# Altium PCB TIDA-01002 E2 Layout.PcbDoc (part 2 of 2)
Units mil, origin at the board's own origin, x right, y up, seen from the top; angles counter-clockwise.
Board outline 1055.12 x 1877.5 mil, 6 copper layers (Layer 1 - Top Layer, Layer 2 - GND, Layer 3 - Signal, Layer 4 - Signal 2, Layer 5 - GND, Layer 6 - Bottom Layer), stack 61.268 mil thick; 83 components, 52 nets, 333 pads, 146 vias.
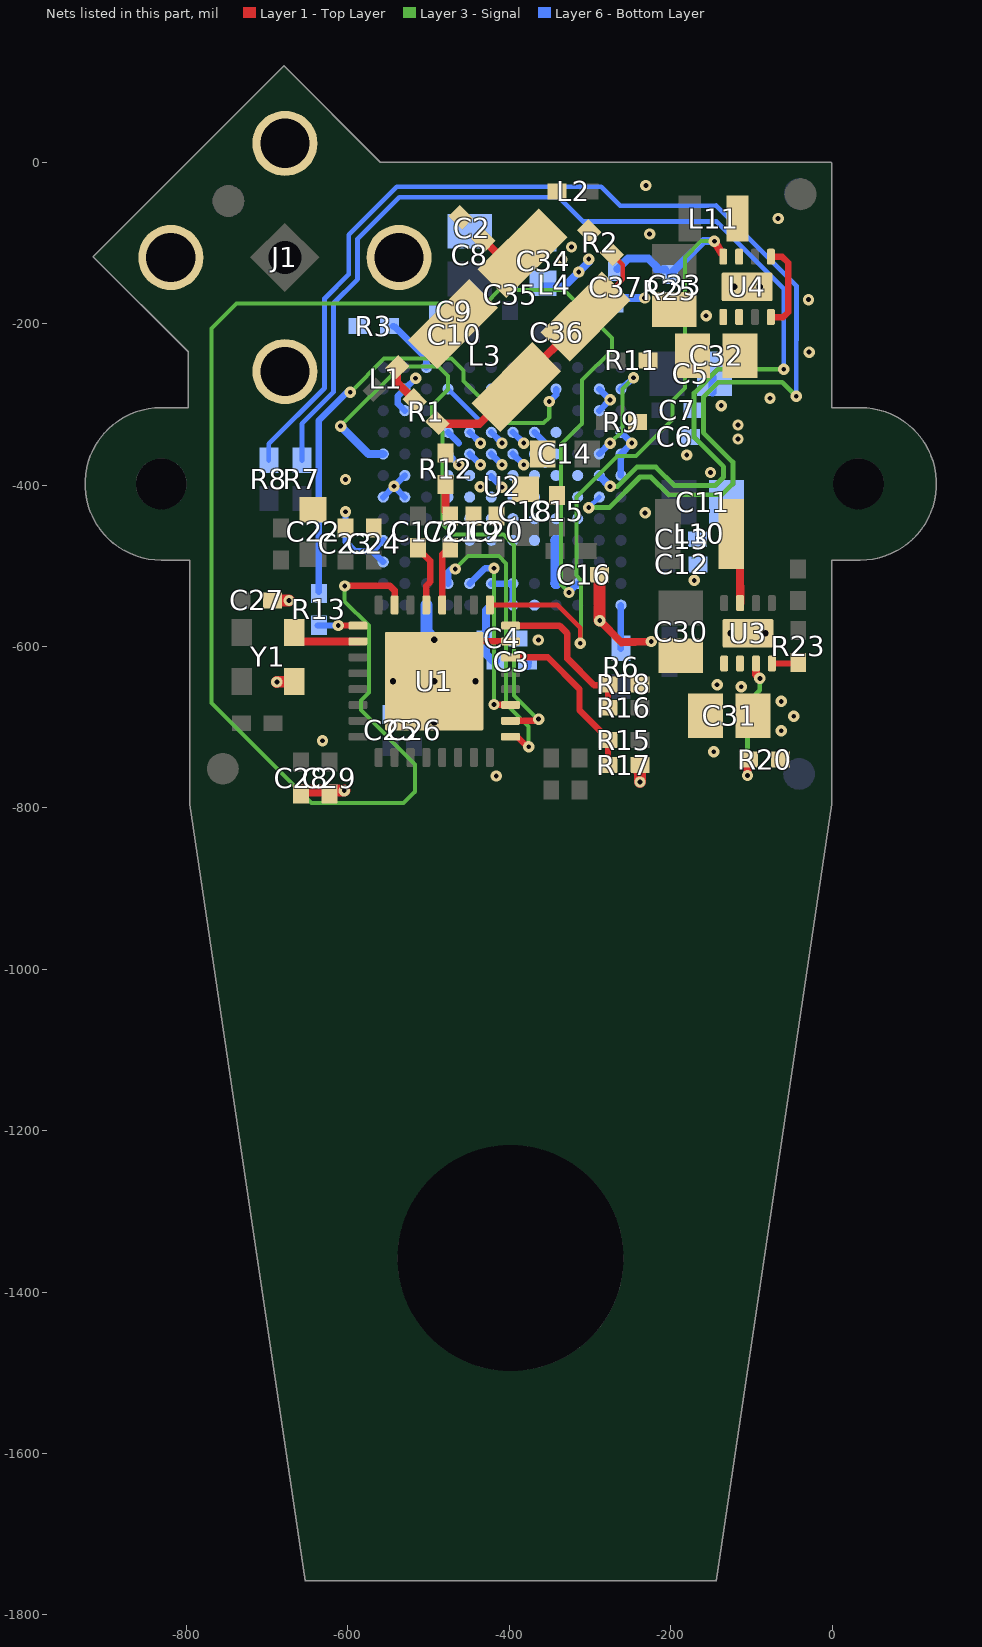
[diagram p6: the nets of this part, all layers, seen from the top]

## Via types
v1: diameter 14, hole 6, Layer 1 - Top Layer to Layer 6 - Bottom Layer, tented both sides, 137 vias
v2: diameter 19.68, hole 7.87, Layer 1 - Top Layer to Layer 6 - Bottom Layer, tented both sides, 5 vias
v3: diameter 19.68, hole 7.87, Layer 1 - Top Layer to Layer 6 - Bottom Layer, 4 vias

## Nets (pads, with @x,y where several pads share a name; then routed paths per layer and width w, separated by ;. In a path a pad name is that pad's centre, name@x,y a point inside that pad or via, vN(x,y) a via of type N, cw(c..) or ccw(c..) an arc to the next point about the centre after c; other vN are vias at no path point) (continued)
GND: C2.2 C3.2 C4.2 C5.2 C6.2 C7.2 C8.2 C9.2 C10.2 C11.2 C12.2 C13.2 C14.2 C15.2 C16.2 C18.2 C19.2 C20.2 C22.2 C23.2 C24.2 C25.2 C26.2 C27.2 C28.2 C29.2 C30.2 C31.2 C32.2 C33.2 C34.2 C35.2 C36.2 C37.2 J1.2 J1.3 J1.4 J1.5 R3.1 R12.2 R17.1 R18.1 R23.1 U1.7 U1.33 U2.A3 U2.A7 U2.A8 U2.B6 U2.B7 U2.B9 U2.C1 U2.D1 U2.D4 U2.D5 U2.D6 U2.D7 U2.D8 U2.D9 U2.E4 U2.E5 U2.E6 U2.E7 U2.E8 U2.E9 U2.E10 U2.F1 U2.F2 U2.F4 U2.F5 U2.F6 U2.F7 U2.F8 U2.F9 U2.F10 U2.G2 U2.G4 U2.G5 U2.G6 U2.G7 U2.G8 U2.G9 U2.G10 U2.G12 U2.H4 U2.H5 U2.H6 U2.H7 U2.H8 U2.H9 U2.H12 U2.J4 U2.J5 U2.J6 U2.J7 U2.J8 U2.J9 U2.J12 U2.K2 U2.K11 U2.L2 U2.L4 U2.L6 U2.L7 U2.L11 U2.M8 U3.1 U3.4 U3.9@-104.2,-583.7 U4.1 U4.4 U4.5 U4.9 Y1.2 | length 1304.7
  Layer 1 - Top Layer w8: U1.33@-443.79,-593.79 U1.7@-398.51,-593.79 ; U4.4@-75.87,-191.8 -60.43,-191.8 -54.5,-185.88 -54.5,-124.5 -62,-117 U4.5@-75.87,-117 ; U3.4@-74.67,-621.1 R23.1@-43.42,-621.1
  Layer 1 - Top Layer w10: v1(-288,-568) -261.2,-594.8 v1(-224.2,-593.9)
  Layer 1 - Top Layer w15: C27.2@-693.32,-543 v1(-673,-543) ; v1(-688,-644) Y1.2@-665.52,-643.51 ; C28.2@-659,-778.69 v1@-604.31,-778.69 ; v1(-288,-568) C16.2@-288,-512 ; R17.1@-238.32,-748 v1(-238,-768)
  Layer 6 - Bottom Layer w6: U2.L4@-475.89,-281.07 -435,-322
  Layer 6 - Bottom Layer w8: v1(-603,-433) -603,-470 -591.14,-481.86 -569.59,-481.86 ; U2.C1@-556.2,-495.24 -569.59,-481.86 ; U2.D1@-556.2,-468.47 -569.59,-481.86 ; U2.F1@-556.2,-414.93 v1(-542.81,-401.54) ; U2.F2@-529.43,-414.93 v1(-542.81,-401.54) ; U2.G2@-529.43,-388.16 v1(-542.81,-401.54) ; U2.K2@-529.43,-307.84 -538,-299.27 -538,-289.64 U2.L2@-529.43,-281.07 v1(-516.04,-267.68) ; U2.H4@-475.89,-361.39 v1(-462.5,-374.77) ; U2.J4@-475.89,-334.61 -462.5,-348 ; U2.H5@-449.11,-361.39 v1(-435.73,-374.77) ; U2.J5@-449.11,-334.61 v1(-435.73,-348) ; U2.G6@-422.57,-389.22 v1(-409.18,-402.61) ; U2.B6@-422.34,-522.02 U2.B7@-395.57,-522.02 U2.A7@-395.57,-548.79 ; U2.H6@-422.34,-361.39 v1(-408.96,-374.77) ; U2.J6@-422.34,-334.61 v1(-408.96,-348) ; U2.L6@-422.34,-281.07 -415.41,-288 -402.5,-288 U2.L7@-395.57,-281.07 -382.18,-267.68 U2.M8@-368.8,-254.3 ; U2.H7@-395.57,-361.39 v1(-382.18,-374.77) ; U2.J7@-395.57,-334.61 v1(-382.18,-348) ; U2.H8@-368.8,-361.39 -355.41,-374.77 ; U2.J8@-368.8,-334.61 -355.41,-348 ; U2.K11@-288.48,-307.84 v1(-275.1,-294.46) U2.L11@-288.48,-281.07 ; U2.G12@-261.71,-388.16 U2.H12@-261.71,-361.39 v1(-248.33,-348) ; U2.J12@-261.71,-334.61 v1(-248.33,-348)
  Layer 6 - Bottom Layer w10: C3.2@-377.31,-624.37 C3.2@-377.31,-619 C3.2@-376.69,-619.63 ; C37.2@-261.61,-168.1 v1(-232.3,-168.1) ; C5.2@-148.47,-285.16 C5.2@-148.47,-266
  Layer 6 - Bottom Layer w14: U2.B9@-342.03,-522.02 U2.D9@-342.03,-468.97
  Layer 6 - Bottom Layer w15: U2.A3@-502.66,-548.79 -502.66,-582.16 v2(-493,-591.82)
  other v1: -604.6,-778.6 -416.2,-760.5 -146.6,-730.5 -631.4,-716.8 -47.5,-686.5 -142.5,-647.5 -364,-592 -170.8,-518.1 -231.7,-434.4 -436,-402 -603,-393 -150.7,-384.4 -180.1,-362.8 -137.4,-301.6 -77,-292.5 -28.46,-235.27 -156.1,-190.2 -29.2,-170.2 -335,-120.5 -323,-105 -226.1,-88.8 -66.9,-69.8 -230.8,-28.7
  other v2: -493,-694.18 -544.18,-643 -493,-643 -441.82,-643
  other v3: -125.85,-583.7 -82.55,-583.7 -121.15,-154.4 -89.65,-154.4
HSYNC: U1.1 U2.B4 | length 358.5
  Layer 1 - Top Layer w8: U1.1@-390.1,-711.9 v1@-376,-726
  Layer 3 - Signal w5: v1(-467,-504) -451,-488 -413,-488 -404,-497 -404,-671 -376,-699 v1@-376,-726
  Layer 6 - Bottom Layer w8: U2.B4@-475.89,-522.02 -475.89,-507.89 -472,-504 v1(-467,-504)
  other v1: -376,-724.2
NetC2_1: C2.1 C34.1 L2.1 L4.2 R2.1 | length 96.3
  Layer 1 - Top Layer w10: C2.1@-432.08,-95.92 L4.2@-415.31,-112.69
  Layer 6 - Bottom Layer w10: C34.1@-358,-154 -332,-154 v1(-314,-136) -301.5,-123.5 v1(-301.5,-120)
NetC3_1: C3.1 C4.1 U2.A6 | length 78.8
  Layer 6 - Bottom Layer w10: U2.A6@-422.34,-548.79 -428.69,-555.13 -428.69,-579 C4.1@-428.69,-590 -428.69,-609.31 -420,-618 C3.1@-416.68,-618
NetC17_2: C17.2 U1.13 | length 79.3
  Layer 1 - Top Layer w8: C17.2@-513.66,-478.34 -498,-494 -498,-520 -502.84,-524.84 U1.13@-502.84,-548.51 ; C17.2@-508,-482.69 C17.2@-507.31,-482.69
NetC21_1: C21.1 R12.1 | length 41.2
  Layer 1 - Top Layer w10: R12.1@-479,-399.49 -479,-432.52 C21.1@-473.2,-438.32
NetC21_2: C21.2 U1.12 | length 69.9
  Layer 1 - Top Layer w8: U1.12@-483.16,-548.51 -483.16,-485.87 C21.2@-478,-480.72
NetC31_1: C31.1 R9.1 R20.1 U3.2
  other v1: -63,-704.5 -63,-668 -112.5,-650 -116.5,-343 -116.5,-325.5
NetC32_1: C32.1 R11.1 U4.2
NetL1_2: L1.2 L3.1 R1.2 | length 50.2
  Layer 1 - Top Layer w10: L1.2@-539.08,-254.08 -539.08,-272.92 R1.2@-516.92,-295.08
NetL3_2: L3.2 L4.1 R1.1 R2.2 | length 341.5
  Layer 1 - Top Layer w6: L4.1@-305.49,-190.91 -259.5,-144.93 -259.5,-127 R2.2@-272.08,-114.42
  Layer 1 - Top Layer w10: R1.1@-489.08,-322.92 -489.08,-324 -437,-324 L3.2@-391.39,-278.61 -391.39,-276.81 L4.1@-305.49,-190.91
NetL10_1: L10.1 U3.7 | length 44.1
  Layer 1 - Top Layer w10: L10.1@-114,-502 U3.7@-113.8,-546.06
NetL11_1: L11.1 U4.7
NetR3_2: R3.2 U2.M3 | length 69.4
  Layer 6 - Bottom Layer w8: R3.2@-544.38,-203 -543,-203 -502.66,-243.34 U2.M3@-502.66,-254.3
NetR6_1: R6.1 U2.A12 | length 54.3
  Layer 6 - Bottom Layer w8: R6.1@-261.71,-603.09 U2.A12@-261.71,-548.79
NetR7_1: R7.1 U2.G11 | length 1424.7
  Layer 3 - Signal w6: v1(-275.1,-401.6) -265.7,-401.6 -241.9,-377.8 -218.3,-377.8 -195.6,-400.5 -145,-400.5 -134.5,-390 -134.5,-377.5 -171,-341 -171,-286 -141.5,-256.5 v1(-60,-256.5)
  Layer 6 - Bottom Layer w6: R7.1@-657,-369.38 -657,-324 -618,-285 -618,-175 -588,-145 -588,-95 -536.4,-43.4 -338.5,-43.5 -308.5,-73.5 -143,-73.5 -60,-156.5 v1(-60,-256.5)
  Layer 6 - Bottom Layer w10: U2.G11@-288.48,-388.16 U2.G11@-288.48,-388.16 v1(-275.1,-401.6)
NetR8_1: R8.1 U2.F11 | length 1568.4
  Layer 3 - Signal w6: v1@-302,-428 -276.04,-428 ; -276,-428 -238.04,-390 -224.6,-390 -202.5,-412.1 -136.5,-412 -123,-398.6 -123,-371.5 -159.5,-335 -159.5,-291 -141,-272.5 -62,-272.5 v1(-44.5,-290)
  Layer 6 - Bottom Layer w6: R8.1@-698,-369.38 -698,-349 -629,-280 -629,-169 -599,-139 -599,-90 -539.5,-30.4 -286,-30.5 -262.7,-53.8 -143.6,-53.7 -44.2,-153.1 v1(-44.5,-290) ; v1@-302,-428 U2.F11@-288.48,-414.93
  other v1: -301.6,-428
NetR13_1: R13.1 U1.17 | length 50.7
  Layer 1 - Top Layer w8: v1(-612,-574) U1.17@-586.49,-574
  Layer 6 - Bottom Layer w8: R13.1@-637.21,-574 v1(-612,-574)
NetR15_1: R15.1 R17.2 U1.6 | length 216.8
  Layer 1 - Top Layer w8: U1.6@-398.51,-613.47 -352.53,-613.47 -313,-653 -313,-679 -277.69,-714.31 R15.1@-277.69,-718 ; R15.1@-283,-718 R15.1@-277.69,-718 ; R17.2@-277.69,-748 R15.1@-277.69,-718
NetR16_1: R16.1 R18.2 U1.8 | length 199.6
  Layer 1 - Top Layer w8: U1.8@-398.51,-574.1 -337.9,-574.1 -328,-584 -328,-615 -295,-648 -277.68,-648 R16.1@-277.68,-678
NetR20_2: R20.2 U3.3 | length 167.2
  Layer 1 - Top Layer w10: v1(-104.8,-759.8) R20.2@-104.8,-739.51 ; U3.3@-94.36,-621.1 -94.15,-634.85 v1(-89.5,-639.5)
  Layer 3 - Signal w6: v1(-104.8,-759.8) -104.8,-669.19 -89.71,-654.1 v1(-89.5,-639.5)
NetU1_18: U1.18 Y1.3 | length 79.7
  Layer 1 - Top Layer w8: Y1.3@-664.53,-587.41 Y1.3@-658.16,-593.79
  Layer 1 - Top Layer w10: Y1.3@-658.16,-593.79 U1.18@-587.49,-593.79
NetU2_H11: U2.H11 U2.L12 | length 133.1
  Layer 3 - Signal w5: v1(-275.1,-348) -260,-333 -260,-281 v1(-246,-267)
  Layer 6 - Bottom Layer w8: U2.H11@-288.48,-361.39 v1(-275.1,-348) ; U2.L12@-261.71,-281.07 v1(-246,-267)
NRST: U1.15 U2.B10 | length 2057.8
  Layer 1 - Top Layer w8: v1(-604,-525) -547.81,-525 -542.21,-530.6 U1.15@-542.21,-550.64
  Layer 3 - Signal w5: v1(-604,-525) -604,-544 -574,-574 -574,-657 -584,-667 -584,-679 -517,-746 -517,-780 -531,-794 -645,-794 -769,-670 -769,-206 -738,-175 -429,-175 -412.5,-158.5 -332,-158.5 -273,-217.5 -273,-233 -310,-270 -310,-324 -336,-350 -336,-523 v1(-326,-533)
  Layer 6 - Bottom Layer w8: v1(-326,-533) U2.B10@-315.26,-522.02
PCLK: U1.3 U2.B5 | length 232.5
  Layer 1 - Top Layer w8: v1@-418.51,-672 U1.3@-393,-672
  Layer 3 - Signal w5: v1(-419,-672) v1(-419,-503)
  Layer 6 - Bottom Layer w8: U2.B5@-449.11,-522.02 -430,-503 v1(-419,-503)
PDB: C37.1 R25.1 U1.9 U4.8 | length 899.7
  Layer 1 - Top Layer w6: U1.9@-424.1,-548.51 -340.5,-548.5 -312,-577 v1(-312,-596)
  Layer 1 - Top Layer w10: v1(-145.9,-97.8) U4.8@-136.5,-113.2
  Layer 3 - Signal w5: v1(-312,-596) -311,-595 -311,-518 -317,-512 -317,-415 -266,-364 -243,-364 -197.81,-318.5 ; -198,-318.5 -198,-295.5 -182.3,-279.8 -182.3,-117.8 -162.3,-97.8 v1(-145.9,-97.8)
  Layer 6 - Bottom Layer w10: C37.1@-266,-132.5 -252.79,-119.28 -227.76,-119.5 -217.8,-129.46 -217.8,-132.72 R25.1@-207.3,-132.72 ; R25.1@-200.9,-139.11 -159.59,-97.8 v1(-145.9,-97.8)
VSYNC: U1.2 U2.H1 | length 798.5
  Layer 1 - Top Layer w8: U1.2@-398.51,-692.21 v1@-363,-692.21
  Layer 3 - Signal w5: v1(-609,-327) -535,-253 -488,-253 -476,-265 -476,-281.5 -496,-301.5 -496,-321 -483,-334 -483,-448 -470,-461 -407,-461 -394,-474 -394,-661 v1@-363,-692
  Layer 6 - Bottom Layer w10: v1(-609,-327) -574.61,-361.39 U2.H1@-556.2,-361.39
  other v1: -363.7,-690
XCLK: R13.2 U2.L9 | length 611.5
  Layer 3 - Signal w5: v1(-597,-285) -555,-243 -471.5,-243 -456.5,-258 -456.5,-271 -404.5,-323 -357.5,-323 -350.5,-316 v1(-350.5,-296.5)
  Layer 6 - Bottom Layer w8: R13.2@-636,-532 -636,-320 -601,-285 v1(-597,-285) ; v1(-350.5,-296.5) -342,-288 U2.L9@-342.03,-281.07
pads on no net: FID1.1 FID2.1 FID3.1 FID4.1 FID5.1 FID6.1 U2.A1 U2.A2 U2.A4 U2.A5 U2.A9 U2.A10 U2.A11 U2.B1 U2.B2 U2.B11 U2.B12 U2.C2 U2.C11 U2.F12 U2.G1 U2.J1 U2.J11 U2.K1 U2.L1 U2.L5 U2.M1 U2.M2 U2.M11 U2.M12 U3.9@-86.48,-583.7 U3.9@-121.92,-583.7

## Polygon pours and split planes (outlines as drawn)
GND on Layer 2 - GND "Layer 2 - GND - GND" (solid, remove dead copper, pour order 4): -763,-798 -1,-798 137,-798 137,142 -923,142 -928,142 -928,-798
GND on Layer 5 - GND "Layer 5 - GND - GND" (solid, remove dead copper, pour order 5): -763,-798 -1,-798 137,-798 137,142 -923,142 -928,142 -928,-798
NetC2_1 on Layer 1 - Top Layer "LAYER_1_-_TOP_LAYER_NETC2_1_P090" (solid, remove dead copper, pour order 90): -277,-96 -277,-118.5 -304,-145.5 -347,-145.5 -364,-128.5 -364,-38 -352,-26 -329,-26 -329,-40.5 -329,-71.5 -301.5,-71.5
1V8 on Layer 1 - Top Layer "LAYER_1_-_TOP_LAYER_1V8_P072" (solid, remove dead copper, pour order 72): -449.11,-467.8 -331.13,-467.8 -331.1,-496.8 -449.11,-496.8
GND on Layer 1 - Top Layer "LAYER_1_-_TOP_LAYER_GND_P066" (solid, remove dead copper, pour order 66): -249.3,-656.4 -202.45,-658.2 -202.45,-694.82 -252.3,-744.68 -252.3,-795.5 -126.2,-795.5 -126.2,-604.3 -81.1,-604.3 -81.1,-635 -68,-635 -68,-577.7 -80.5,-565.2 -135.54,-565.2 -135.54,-585.2 -249.3,-585.2
NetC31_1 on Layer 1 - Top Layer "LAYER_1_-_TOP_LAYER_NETC31_1_P064" (solid, remove dead copper, pour order 64): -21.39,-642.1 -21.39,-751.5 -77.6,-751.5 -77.6,-716.5 -120.4,-716.5 -120.4,-642.1 -120.4,-611 -110.2,-611 -110.2,-642.1
1V8_VDDPLL on Layer 1 - Top Layer "AutoNaming" (solid, remove dead copper, pour order 14): -331,-344.3 -331,-394 -331,-426 -347.5,-442.5 -351.21,-442.5 -351.21,-457 -351,-462 -351,-512 -433.11,-512 -449.11,-528 -449.11,-558.11 -439,-558.11 -413,-538 -337.2,-538.11 -336,-522.02 -315.26,-522.02 -296,-492.99 -296,-457 -270,-431 -270,-381 -270,-344.3
2V8 on Layer 1 - Top Layer "LAYER_1_-_TOP_LAYER_2V8_P060" (solid, remove dead copper, pour order 60): -290.16,-373.36 -290.16,-579 -137.1,-579 -137.1,-560.8 -154.1,-543.8 -185.4,-512.5 -185.4,-419.4 -168.8,-402.8 -168.8,-382.7 -198,-353.5 -270.3,-353.5
GND on Layer 1 - Top Layer "LAYER_1_-_TOP_LAYER_GND_P074" (solid, remove dead copper, pour order 74): -585.5,-96 -585.5,-155 -564.5,-176 -498.7,-176 -418.35,-95.65 -462.5,-51.5 -541,-51.5
1V8 on Layer 1 - Top Layer "LAYER_1_-_TOP_LAYER_1V8_P078" (solid, remove dead copper, pour order 78): -109.1,-7.1 -66.1,-50.1 -66.1,-96.9 -95,-96.9 -96.6,-95.3 -96.6,-34.9 -138.2,-34.9 -138.2,-83.25 -151.05,-83.25 -151.05,-144.74 -168.9,-144.74 -246.7,-144.74 -246.7,-116.3 -264,-99 -264,-7.1
GND on Layer 1 - Top Layer "LAYER_1_-_TOP_LAYER_GND_P080" (solid, remove dead copper, pour order 80): -240.2,-151.3 -240.2,-171.6 -223.9,-187.9 -223.9,-203.2 -213.43,-213.68 -213.43,-268.3 -143.5,-268.3 -143.5,-209.1 -137.6,-203.2 -131,-203.2 -131,-170.55 -84.5,-170.55 -84.5,-191.8 -69.5,-191.8 -69.5,-171.6 -73.5,-167.6 -73.5,-138 -75,-136.5 -132,-136.5 -146.8,-151.3
NetC32_1 on Layer 1 - Top Layer "LAYER_1_-_TOP_LAYER_NETC32_1_P082" (solid, remove dead copper, pour order 82): -243.6,-271.3 -243.6,-304.01 -92.6,-304.01 -92.6,-213 -96.8,-213 -109,-200.8 -109,-178.8 -121.6,-178.8 -121.6,-199.7 -134.9,-213 -134.9,-274.8 -218.17,-274.8 -218.17,-234.87 -243.6,-234.87
"9V IN" on Layer 1 - Top Layer "LAYER_1_-_TOP_LAYER_9V_IN_P094" (solid, remove dead copper, pour order 94): -316.5,-192 -316.5,-333.5 -224.5,-333.5 -224.5,-192
NetC31_1 on Layer 1 - Top Layer "LAYER_1_-_TOP_LAYER_NETC31_1_P100" (solid, remove dead copper, pour order 100): -252.5,-307 -252.5,-356 -102.5,-356 -88,-341.5 -88,-320 -101,-307
GND on Layer 6 - Bottom Layer "LAYER_6_-_BOTTOM_LAYER_GND_P068" (solid, remove dead copper, pour order 68): -109.6,-235 -109.6,-530.1 -189.7,-530.1 -189.7,-235
2V8 on Layer 6 - Bottom Layer "LAYER_6_-_BOTTOM_LAYER_2V8_P058" (solid, remove dead copper, pour order 58): -247.3,-171.62 -247.3,-281.8 -269,-303.5 -269,-318.5 -252.6,-326.63 -252.6,-485.2 -203.9,-533.9 -185.2,-533.9 -185.2,-457.3 -172,-457.3 -172,-166 -241.68,-166
1V8 on Layer 6 - Bottom Layer "LAYER_6_-_BOTTOM_LAYER_1V8_P054" (solid, remove dead copper, pour order 54): -517.6,-287 -517.6,-448.6 -487.7,-448.6 -487.7,-326.7 -480.3,-319.3 -465.2,-319.3 -465.2,-287
1V8 on Layer 6 - Bottom Layer "LAYER_6_-_BOTTOM_LAYER_1V8_P032" (solid, remove dead copper, pour order 32): -420.5,-124.5 -465.5,-124.5 -465.5,-159 -465.5,-222 -420.5,-222
GND on Layer 6 - Bottom Layer "LAYER_6_-_BOTTOM_LAYER_GND_P076" (solid, remove dead copper, pour order 76): -530.1,-51.1 -580.1,-101.1 -451.1,-101.1 -414,-101.1 -414,-160.2 -376.95,-160.2 -371,-160.2 -366.7,-160.2 -342.9,-160.2 -333.55,-169.55 -333.55,-221 -309.45,-221 -258,-169.55 -262.95,-169.55 -286.25,-146.25 -286.25,-119.25 -354.4,-51.1
GND on Layer 6 - Bottom Layer "LAYER_6_-_BOTTOM_LAYER_GND_P086" (solid, remove dead copper, pour order 86): -672.3,-762.15 -672.35,-795.5 -589.6,-795.5 -589.6,-762.22
NetC31_1 on Layer 3 - Signal "LAYER_3_-_SIGNAL_NETC31_1_P098" (solid, remove dead copper, pour order 98): -19.59,-361.41 -19.59,-516.36 -19.59,-795.5 -256,-795.5 -256,-308.25 -72.76,-308.24
"9V IN" on Layer 3 - Signal "LAYER_3_-_SIGNAL_9V_IN_P092" (solid, remove dead copper, pour order 92): -319.5,-63 -319.5,-159 -248,-230.5 -235,-230.5 -221,-216.5 -221,-83.63 -255.63,-49 -305.5,-49
1V8 on Layer 4 - Signal 2 "LAYER_4_-_SIGNAL_2_1V8_P050" (solid, remove dead copper, pour order 50): -776.11,-20.2 -776.11,-463.19 -770.95,-468.35 -603.24,-468.45 -395.64,-676.05 -207.95,-676.05 -190.1,-658.2 -190.1,-632.8 -208.6,-614.3 -306.7,-614.3 -312,-609 -312,-451.55 -400.7,-362.85 -400.7,-230.1 -385.47,-214.87 -38.36,-214.87 -21,-232.23 -21,-109.55 -21,-20.2
2V8 on Layer 4 - Signal 2 "LAYER_4_-_SIGNAL_2_2V8_P048" (solid, remove dead copper, pour order 48): -775.6,-480 -775.6,-797.3 -21.6,-797.6 -21.33,-565.2 -139.32,-565.2 -139.32,-577.1 -160.72,-577.1 -160.72,-555.25 -145.7,-540.23 -145.7,-518.75 -136.55,-509.6 -90.3,-509.6 -77.3,-522.6 -77.3,-565.2 -21.34,-565.2 -21.34,-242.4 -42.03,-221.7 -183.4,-221.7 -189.9,-217.75 -212.35,-217.75 -216.31,-221.7 -384.3,-221.7 -393.4,-230.8 -393.4,-358.8 -295.2,-457 -295.2,-598.77 -286.93,-607.09 -201.09,-607.57 -183.4,-625.36 -183.4,-664.4 -202.4,-683.4 -395.1,-683.4 -603,-475.5 -771.1,-475.5

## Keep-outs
Keep-Out Layer:
  lines w10: -920.75,-117 cw(c-915.75,-117) -919.29,-113.46 -919.27,-113.45 ; -920.75,-117 cw(c-915.75,-117) -919.27,-113.45 ; -920.75,-117 ccw(c-915.75,-117) -919.29,-120.54 -919.27,-120.55 ; -920.75,-117 ccw(c-915.75,-117) -919.27,-120.55 ; -919.27,-120.55 -802.88,-236.94 -802.88,-299.01 -831.32,-299.01 ; -919.27,-113.45 -682.8,123.02 ; -831.37,-497.99 ccw(c-831.32,-492.99) -831.32,-497.99 ; -831.37,-497.99 cw(c-831.32,-398.5) -930.81,-398.5 cw(c-831.32,-398.5) -831.37,-299.01 ; -831.37,-497.99 ccw(c-831.32,-398.5) -831.32,-497.99 ; -831.37,-497.99 ccw(c-831.32,-492.99) -831.32,-497.99 ; -831.37,-299.01 cw(c-831.32,-304.01) -831.32,-299.01 ; -831.37,-299.01 cw(c-831.32,-304.01) -831.32,-299.01 ; -831.37,-299.01 cw(c-831.32,-398.5) -831.32,-299.01 ; -831.32,-497.99 ccw(c-831.32,-492.99) -831.32,-497.99 ; -831.32,-497.99 -800.89,-497.99 -800.89,-795.41 ; -831.32,-299.01 ccw(c-831.32,-304.01) -831.32,-299.01 ; -800.89,-796.14 ccw(c-795.89,-796.14) -800.89,-796.14 ; -800.89,-796.14 ccw(c-795.89,-796.14) -800.6,-797.81 ; -800.89,-796.14 ccw(c-795.89,-796.14) -800.6,-797.81 ; -800.89,-796.14 -800.89,-795.59 ; -800.89,-796.14 -800.89,-795.51 ; -800.89,-795.59 cw(c-795.89,-795.5) -800.89,-795.51 ; -800.89,-795.59 -800.89,-795.41 ; -800.89,-795.5 ccw(c-795.89,-795.5) -800.89,-795.51 ; -800.89,-795.5 cw(c-795.89,-795.5) -800.89,-795.41 ; -800.89,-795.5 ccw(c-795.89,-795.5) -800.89,-795.51 ; -800.89,-795.5 cw(c-795.89,-795.5) -800.89,-795.41 ; -800.6,-797.81 -657.95,-1758.73 ; -682.8,123.02 cw(c-679.25,119.5) -675.71,123.04 -675.7,123.02 ; -682.8,123.02 -682.79,123.04 cw(c-679.25,119.5) -675.7,123.02 ; -675.7,123.02 -557.81,5.13 -1.61,5.13 ; -657.95,-1758.73 ccw(c-653,-1758) -653,-1763 ; -657.95,-1758.73 ccw(c-653,-1758) -653,-1763 ; -653,-1763 -143.5,-1763 ; -143.5,-1763 ccw(c-143.5,-1758) -138.56,-1758.73 ; -143.5,-1763 ccw(c-143.5,-1758) -138.56,-1758.73 ; -138.56,-1758.73 4.1,-797.81 ; -1.61,5.13 cw(c-1.61,0.13) 1.95,3.65 ; -1.61,5.13 cw(c-1.61,0.13) 1.93,3.67 ; 1.93,3.67 1.95,3.65 ; 1.95,3.65 2.91,2.69 ; 2.91,2.69 cw(c-0.61,-0.86) 4.39,-0.86 ; 2.91,2.69 2.92,2.67 cw(c-0.61,-0.86) 4.39,-0.86 ; 4.1,-797.81 ccw(c-0.61,-796.14) 4.39,-796.14 ; 4.1,-797.81 ccw(c-0.61,-796.14) 4.39,-796.14 ; 4.39,-796.14 ccw(c-0.61,-796.14) 4.39,-796.14 ; 4.39,-796.14 4.39,-795.57 ; 4.39,-796.14 4.39,-795.5 ; 4.39,-795.57 ccw(c-0.61,-795.5) 4.39,-795.5 ; 4.39,-795.57 4.39,-795.43 ; 4.39,-795.5 ccw(c-0.61,-795.5) 4.39,-795.43 ; 4.39,-795.5 ccw(c-0.61,-795.5) 4.39,-795.43 ; 4.39,-795.43 4.39,-497.99 34.82,-497.99 ; 4.39,-0.86 4.39,-299.01 34.82,-299.01 ; 34.82,-497.99 ccw(c34.82,-398.5) 34.87,-497.99 ; 34.82,-497.99 ccw(c34.82,-492.99) 34.87,-497.99 ; 34.82,-497.99 ccw(c34.82,-492.99) 34.87,-497.99 ; 34.82,-299.01 cw(c34.82,-304.01) 34.87,-299.01 ; 34.82,-299.01 cw(c34.82,-398.5) 34.87,-299.01 ; 34.87,-497.99 ccw(c34.82,-398.5) 34.87,-299.01
  text ".Layer_Name" at -346,-2616.49 h60

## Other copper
Layer 1 - Top Layer:
  region net NetL11_1: -110.3,-124.9 -110.3,-98.4 -103.6,-98.4 -103.6,-41.4 -131.2,-41.4 -131.2,-98.4 -120.2,-98.4 -120.2,-124.9
  region net GND: -558,-466 -613,-466 -632,-447 -660,-447 -660,-414 -632,-386 -593,-386 -558,-421
  region net GND: -454,-450.2 -454,-394 -475,-373 -488.1,-373 -490,-371.1 -490,-348.8 -482.2,-341 -342.03,-341 -342.03,-390.97 -331.2,-401.8 -331.2,-429.65 -336.55,-435 -358,-435 -398.6,-435 -405.6,-442 -405.6,-450.2
  region net NetL1_2: -558,-253 -540.5,-270.5 -523,-253 -497,-253 -491.5,-258.5 -472,-239 -491.1,-219.9 -508,-203
  region net DOUTP: -523,-437 -523,-451 -503,-451 -503,-437
  region net GND: -456.68,-603 -350.96,-603 -350.96,-585 -430,-585 -433,-582 -456.68,-582
  text ".Layer_Name" at -346,-2616.49 h60
Layer 2 - GND:
  text ".Layer_Name" at -346,-2616.49 h60
Layer 3 - Signal:
  text ".Layer_Name" at -346,-2616.49 h60
Layer 4 - Signal 2:
  rectangle net 2V8: -67.94,-575.5 -21.35,-554.5
  text ".Layer_Name" at -346,-2616.49 h60
Layer 5 - GND:
  text ".Layer_Name" at -346,-2616.49 h60
Layer 6 - Bottom Layer:
  region net GND: -459.67,-327.5 -417.05,-327.5 -417.05,-294.3 -398.9,-294.3 -372.4,-267.8 -381.8,-258.4 -404.34,-280.94 -413.61,-280.94 -419.85,-274.7 -428.46,-283.31 -428.46,-297.7 -442.85,-297.7 -459.67,-314.52
  region net GND: -544,-697 -521,-697 -505,-697 -498,-704 -481.58,-704 -481.58,-672 -557,-672 -557,-697
  region net GND: -483,-224.77 -483,-107.5 -440,-107.5 -440,-90 -503,-90 -518,-75 -554,-75 -580,-101 -580,-155 -608,-183 -608,-216 -575,-216 -575,-190 -564.5,-179.5 -504.5,-179.5 -501,-183 -501,-224.77
  region net GND: -403,-541 -403,-600 -394,-600 -390,-604 -390,-629 -362,-629 -341,-608 -341,-597 -341,-589 -361,-569 -361,-542 -376,-542 -388,-530 -388,-515 -429,-515 -429,-529 -415,-529
  region net GND: -483,-476 -335,-476 -335,-449 -308,-449 -308,-439.3 -314,-433.3 -314,-423 -308,-417 -308,-412.9 -308,-381.5 -335,-381.5 -335,-327 -483,-327 -483,-444 -477,-450 -477,-460 -483,-466
  text ".Layer_Name" at -346,-2616.49 h60

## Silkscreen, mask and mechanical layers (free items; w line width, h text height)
Top Overlay:
  text ".Layer_Name" at -346,-2616.49 h60
Bottom Overlay:
  text "TIDA-01002" at -265,-923 h60
  text ".Layer_Name" at -346,-2616.49 h60
Top Paste:
  text ".Layer_Name" at -346,-2616.49 h60
Bottom Paste:
  text ".Layer_Name" at -346,-2616.49 h60
Top Solder:
  text ".Layer_Name" at -346,-2616.49 h60
  text ".Layer_Name" at -346,-2616.49 h60
Bottom Solder:
  text ".Layer_Name" at -346,-2616.49 h60
Drill Guide:
  text ".Layer_Name" at -346,-2616.49 h60
M1 Board Outline:
  lines w10: -795.89,-796.14 -795.89,-492.99 -831.32,-492.99 cw(c-831.32,-398.5) -831.32,-304.01 -797.88,-304.01 -797.88,-234.87 -915.75,-117 -679.25,119.5 -559.88,0.13 -1.61,0.13 ; -795.89,-795.5 -653,-1758 -143.5,-1758 -0.61,-795.5 ; -791.22,-820.5 -764.27,-820.5 ; -732.27,-820.5 -700.63,-820.5 ; -668.63,-820.5 -636.99,-820.5 ; -604.99,-820.5 -573.35,-820.5 ; -541.35,-820.5 -509.72,-820.5 ; -477.72,-820.5 -446.08,-820.5 ; -414.08,-820.5 -382.44,-820.5 ; -408.27,-859.5 -391.27,-859.5 ; -398.27,-907.5 -398.27,-867.5 ; -350.44,-820.5 -318.8,-820.5 ; -286.8,-820.5 -255.16,-820.5 ; -223.16,-820.5 -191.53,-820.5 ; -159.53,-820.5 -127.89,-820.5 ; -95.89,-820.5 -64.25,-820.5 ; -32.25,-820.5 -5.25,-820.5 ; -0.61,-796.14 -0.61,-492.99 34.82,-492.99 ccw(c34.82,-398.5) 34.82,-304.01 -0.61,-304.01 -0.61,-0.86 ; -418.27,-867.5 -378.27,-867.5 -398.27,-847.5 -418.27,-867.5
  text "V-SCORE" at -558.27,-976.5 h75
  text ".Layer_Name" at -346,-2616.49 h60
M2 Board Dimensions:
  rectangle: -798,-2158 -423,-2033
  rectangle: -923,-2033 -798,-1908
  lines w7: -923,-2033 77,-2033 ; -798,-2158 -798,-1908 ; -673,-2158 -673,-1908 ; -423,-2158 -423,-1908 ; -173,-2158 -173,-1908 ; -923,-2158 -923,-1908 77,-1908 77,-2158 -923,-2158
  text ".Layer_Name" at -346,-2616.49 h60
M3 3D STEP Top:
  text ".Layer_Name" at -346,-2616.49 h60
M4 3D STEP Bottom:
  text ".Layer_Name" at -346,-2616.49 h60
M5 Assembly Top:
  lines w10: -1215,-2688.17 5385,-2688.17 ; -1215,-2484.83 5387,-2484.83 ; -1215,-2281.5 -1215,-2891.5 2790,-2891.5 5387,-2891.5 5387,-2281.5 -1214.5,-2281.5 -1214.5,-2891.5 361,-2891.5 ; 1250,-2891.5 1250,-2281.5 ; 2517,-2484.83 2517,-2281.5 ; 3357,-2484.83 3357,-2281.5 ; 3979,-2898 3979,-2695.17
  text "COMPONENTS MARKED 'DNP' SHOULD NOT BE POPULATED." at 230.5,-2076.5 h60
  text "ASSEMBLY VARIANT:" at 230,-2192 h60
  text ".VariantName" at 1266,-2192 h60
  text "PCB VIEWED FROM TOP SIDE" at -1151.5,-2413.67 h60
  text "BOARD #:" at 1325,-2413.67 h60
  text ".PRJ_Number" at 1870.5,-2413.67 h60
  text "REV:" at 2715,-2413.67 h60
  text ".PCB_Rev" at 3006.5,-2413.67 h60
  text "SVN REV:" at 3553,-2413.67 h60
  text ".VersionControl_RevNumber" at 4059,-2413.67 h60
  text "TID #:" at 1325,-2617 h60
  text ".TID" at 1870.5,-2617 h60
  text "PLOT NAME =" at -1151.5,-2822.34 h60
  text ".plot_File_Name" at -346,-2822.34 h60
  text "GENERATED    :" at 1327,-2822.34 h60
  text ".Print_Date" at 2196.5,-2822.34 h60
  text ".Print_Time" at 2925.5,-2822.34 h60
  text "TEXAS INSTRUMENTS" at 4190,-2822.34 h60
M6 Assembly Bottom:
  lines w10: -1215.5,-2485.33 5386.5,-2485.33 ; -1213.5,-2688.67 5386.5,-2688.67 ; 192.5,-2898.5 192.5,-2695.67 ; 814.5,-2485.33 814.5,-2282 ; 1654.5,-2485.33 1654.5,-2282 ; 2921.5,-2892 2921.5,-2282 ; 3810.5,-2892 5386,-2892 5386,-2282 -1215.5,-2282 -1215.5,-2892 1381.5,-2892 5386.5,-2892 5386.5,-2282
  text "COMPONENTS MARKED 'DNP' SHOULD NOT BE POPULATED." at 5179,-2076 h60
  text ".VariantName" at 4135,-2192 h60
  text "ASSEMBLY VARIANT:" at 5174,-2192 h60
  text ".VersionControl_RevNumber" at 112.5,-2414.17 h60
  text "SVN REV:" at 618.5,-2414.17 h60
  text ".PCB_Rev" at 1165,-2414.17 h60
  text "REV:" at 1456.5,-2414.17 h60
  text ".PRJ_Number" at 2301,-2414.17 h60
  text "BOARD #:" at 2846.5,-2414.17 h60
  text "PCB VIEWED FROM BOTTOM SIDE" at 5323,-2414.17 h60
  text ".TID" at 2301,-2617.5 h60
  text "TID #:" at 2846.5,-2617.5 h60
  text "TEXAS INSTRUMENTS" at -18.5,-2822.84 h60
  text ".Print_Time" at 1246,-2822.84 h60
  text ".Print_Date" at 1975,-2822.84 h60
  text "GENERATED    :" at 2844.5,-2822.84 h60
  text ".plot_File_Name" at 4517.5,-2822.84 h60
  text "PLOT NAME =" at 5323,-2822.84 h60
M9 Title Sheet:
  drawing of 57 lines, arcs and shapes, not listed
  text "1" at -183.16,6278.5 h70
  text "2" at 2312.5,6278.5 h70
  text "3" at 4801.84,6278.5 h70
  text "4" at 7308.51,6278.5 h70
  text "5" at 9807.5,6278.5 h70
  text "6" at 12312.5,6278.5 h70
  text "A" at -1339.5,5135.5 h70
  text "A" at 13460.5,5135.5 h70
  text "B" at -1339.5,2755.5 h70
  text "B" at 13460.5,2755.5 h70
  text "C" at -1339.5,380.5 h70
  text "C" at 13460.5,380.5 h70
  text "PROJECT TITLE:" at 10420.5,-1480.5 h45
  text ".PRJ_Title" at 10470.5,-1613.83 h60
  text "DESIGNED FOR:" at 10420.5,-1781.5 h45
  text ".PRJ_Customer" at 10470.5,-1921.5 h70
  text "D" at -1339.5,-1989.5 h70
  text "D" at 13460.5,-1989.5 h70
  text "FILE NAME:" at 10420.5,-2081.5 h45
  text ".PCB_File_Name_No_Path" at 10470.5,-2201.5 h70
  text "Texas Instruments (TI) and/or its licensors do not warrant the accuracy or completeness of this specification" at 5451,-2363.34 h45
  text "ENGINEER:" at 10420.5,-2371.5 h45
  text "LAYOUT BY:" at 11925.5,-2371.5 h45
  text "or any information contained therein. TI and/or its licensors do not warrant that this design will meet" at 5406.01,-2476 h45
  text ".PRJ_Engineer" at 10470.5,-2526.49 h70
  text ".PCB_Layout" at 11976,-2526.49 h70
  text "the specifications, will be suitable for your application or fit for any particular purpose, or will operate in" at 5406.01,-2588.67 h45
  text ".Layer_Name" at -346,-2616.49 h60
  text "ALTIUM DESIGNER VERSION:" at 11925.5,-2681.5 h45
  text "an implementation. TI and/or its licensors do not warrant that the design is production worthy. You should" at 5406.01,-2701.33 h45
  text "completely validate and test your design implementation to confirm the system functionality for your application." at 5451,-2814 h45
  text ".print_Scale" at 10470.5,-2814.83 h70
  text ".Application_BuildNumber" at 11976,-2814.83 h70
  text "1" at -183.16,-3021.5 h70
  text "2" at 2312.5,-3021.5 h70
  text "3" at 4801.84,-3021.5 h70
  text "4" at 7308.51,-3021.5 h70
  text "5" at 9807.5,-3021.5 h70
  text "6" at 12312.5,-3021.5 h70
M10 Fab Notes:
  drawing of 173 lines, arcs and shapes, not listed
  text "DESIGN INFORMATION" at 11455.02,4443 h60
  text "MIN. TRACK WIDTH:" at 10810.46,4263 h60
  text "5" at 11906.7,4263 h60
  text "MIL" at 12061.46,4263 h60
  text "MIN. CLEARANCE:" at 10810.46,4131 h60
  text "5" at 11846.7,4131 h60
  text "MIL" at 12061.46,4131 h60
  text "MIN. VIA PAD SIZE:" at 10810.46,3999 h60
  text "14" at 11876.71,3999 h60
  text "MIL" at 12061.46,3999 h60
  text "TOP layer contains 50 Ohm single-ended trace with 20MIL wide line (J1 to C17)." at 5412,3911 h60
  text "0.05mm (2MIL)" at 11505.46,3857.29 h60
  text "MINIMUM ANNULAR RING" at 10481.23,3853 h60
  text "EXTERNAL" at 12213.46,3853 h60
  text "PER" at 10681.23,3735 h60
  text "IPC-D-275 CLASS 2 LEVEL C" at 10901.23,3735 h60
  text "MIL, HOLES" at 12389.46,3622.71 h60
  text "+/-" at 11997,3622 h60
  text "+/-" at 12851,3622 h60
  text "REGISTRATION TOLERANCES:" at 10481.23,3617 h60
  text "METAL" at 11681,3617 h60
  text "5" at 12257.2,3617 h60
  text "3" at 13090.2,3617 h60
  text "MIL" at 13206.46,3617 h60
  text "+/-" at 12851,3504 h60
  text "HOLE SIZE TOLERANCE (UNLESS OTHERWISE SPECIFIED):" at 10481.23,3499 h60
  text "3" at 13090.2,3499 h60
  text "MIL" at 13206.46,3499 h60
  text "MATERIAL:" at 10406.46,3289.54 h60
  text "FR-4 High Tg" at 11392.9,3149.21 h60
  text "370HR" at 12683.46,3146.64 h60
  text "FR-408" at 10827.46,3140.64 h60
  text "OTHER" at 12315.46,3140.64 h60
  text "X" at 12131,3139 h60
  text "62 MIL (1.6mm) +/-10%" at 11147.56,2977.92 h60
  text "THICKNESS:" at 10481.23,2973.64 h60
  text "X" at 11019.4,2973.64 h60
  text "OTHER" at 12432.46,2973.64 h60
  text "TOLERANCE:" at 10481.23,2815.64 h60
  text "X" at 11320.53,2815.64 h60
  text "ANSI IPC-6012 TYPE 3 CLASS 2" at 11507.48,2815.64 h60
  text "OTHER +/-" at 11507.46,2659.64 h60
  text "BOW & TWIST:" at 10481.23,2502.64 h60
  text "X" at 11320.53,2502.64 h60
  text "ANSI IPC-6012 TYPE 3 CLASS 2" at 11507.48,2502.64 h60
  text "OTHER +/-" at 11507.46,2344.13 h60
  text "DRILLING:" at 10406.46,2205.64 h60
  text "REFERENCE:" at 10481.23,2088.64 h60
  text "X" at 11129.46,2088.64 h60
  text "AS SHOWN" at 11316.46,2088.64 h60
  text "X" at 12030.46,2088.64 h60
  text "NC_DRILL FILES" at 12167.46,2088.64 h60
  text "PTH COPPER THICKNESS:" at 10481.23,1930.64 h60
  text "X" at 11611.46,1930.64 h60
  text "20-30 um" at 11748.46,1930.64 h60
  text "OTHER" at 12465.46,1930.64 h60
  text "BOARD FINISH:" at 10406.46,1771.64 h60
  text "SILKSCREEN:" at 10561.68,1653.64 h60
  text "X" at 11510.46,1653.64 h60
  text "TOP" at 11636.46,1653.64 h60
  text "X" at 12020.46,1653.64 h60
  text "BOTTOM" at 12147.46,1653.64 h60
  text "SILKSCREEN COLOR:" at 10561.68,1486.64 h60
  text "X" at 11509.42,1486.64 h60
  text "WHITE" at 11636.46,1486.64 h60
  text "OTHER" at 12147.46,1486.64 h60
  text "BLACK" at 12890.46,1336.44 h60
  text "X" at 12231,1330 h60
  text "GREEN" at 11767.46,1327.44 h60
  text "OTHER" at 12385.46,1327.44 h60
  text "SOLDER RESIST COLOR:" at 10561.68,1316.64 h60
  text "X" at 12230,1159 h60
  text "MATTE" at 11767.46,1157.44 h60
  text "SEMI-GLOSS" at 12385,1156.8 h60
  text "IMMERSION GOLD (ENIG)" at 11467.46,968.92 h60
  text "ENEPIG" at 12805,965.64 h60
  text "SURFACE FINISH:" at 10406.46,964.64 h60
  text "X" at 11280.51,964.64 h60
  text "IMM. TIN/SILVER OR EQUIV" at 10736,807.64 h60
  text "OTHER" at 12167.46,807.64 h60
  text "ARRAY/PANEL:" at 10406.46,628.64 h60
  text "CUT AND TRIM PER M1 BOARD OUTLINE" at 11467.46,624.35 h60
  text "N.C. ROUTE" at 11467.46,472.64 h60
  text "X" at 12146.46,472.64 h60
  text "V. SCORE" at 12333.46,472.64 h60
  text "CERTIFICATION:" at 10406.46,335.64 h60
  text "MATERIALS AND WORKMANSHIP FOR ALL PCBS" at 11131.46,335.64 h60
  text "TO MEET OR EXCEED THE REQUIREMENTS OF:" at 11131.46,237.64 h60
  text "X" at 10757.96,101.13 h60
  text "ANSI IPC-A-600F CLASS ->" at 10896.96,101.13 h60
  text "X" at 12536.02,101.13 h60
  text "2" at 12654.96,101.14 h60
  text "1" at 12339.96,99.64 h60
  text "3" at 13008.96,99.64 h60
  text "X" at 11572.02,-58.36 h60
  text "RoHS" at 11708.96,-58.36 h60
  text "OTHER" at 12353.36,-58.36 h60
  text "PER ORDER" at 12750.42,-58.36 h60
  text "ALL BOARDS MUST MEET OR EXCEED UL94-V0 REQUIREMENTS." at 10434,-224 h60
  text "PCB MUST BEAR THE UL94V-0 UL REGISTERED MATERIAL ID NUMBER" at 10434,-344 h60
  text "ADDITIONAL REQUIREMENTS:" at 10406.46,-517.36 h60
  text "MICROSECTION:" at 10481.23,-632.36 h60
  text "YES" at 11386.96,-632.36 h60
  text "REQUIRED" at 12248.46,-788.51 h60
  text "BARE BOARD ELEC. TEST:" at 10481.23,-791.36 h60
  text "NONE" at 11786.96,-791.36 h60
  text "X" at 12121.46,-791.36 h60
  text "PER ORDER" at 12840.46,-791.36 h60
  text ".Layer_Name" at -346,-2616.49 h60
M11 Gerber Information:
  lines w10: -1215,-2688.17 5385,-2688.17 ; -1215,-2484.83 5387,-2484.83 ; -1215,-2281.5 -1215,-2891.5 2790,-2891.5 5387,-2891.5 5387,-2281.5 -1214.5,-2281.5 -1214.5,-2891.5 361,-2891.5 ; 1250,-2891.5 1250,-2281.5 ; 2517,-2484.83 2517,-2281.5 ; 3357,-2484.83 3357,-2281.5 ; 3979,-2898 3979,-2695.17
  text "ALL ARTWORK VIEWED FROM TOP SIDE" at -1151.5,-2413.67 h60
  text "BOARD #:" at 1325,-2413.67 h60
  text ".PRJ_Number" at 1870.5,-2413.67 h60
  text "REV:" at 2715,-2413.67 h60
  text ".PCB_Rev" at 3006.5,-2413.67 h60
  text "SVN REV:" at 3553,-2413.67 h60
  text ".VersionControl_RevNumber" at 4059,-2413.67 h60
  text "LAYER NAME =" at -1151.5,-2616.49 h60
  text "TID #:" at 1325,-2617 h60
  text ".TID" at 1870.5,-2617 h60
  text "PLOT NAME =" at -1151.5,-2822.34 h60
  text ".plot_File_Name" at -346,-2822.34 h60
  text "GENERATED    :" at 1327,-2822.34 h60
  text ".Print_Date" at 2196.5,-2822.34 h60
  text ".Print_Time" at 2925.5,-2822.34 h60
  text "TEXAS INSTRUMENTS" at 4190,-2822.34 h60
M12 Stackup:
  drawing of 399 lines, arcs and shapes, not listed
  text "Layer" at 5134.5,5929.5 h60
  text "Name" at 5544.41,5929.5 h60
  text "Material" at 6954,5929.5 h60
  text "Thickness" at 7813.77,5929.5 h60
  text "Constant" at 8463.6,5929.5 h60
  text "Board Layer Stack" at 9033.46,5929.5 h60
  text "1" at 5134.5,5809.5 h60
  text "Top Overlay" at 5544.41,5809.5 h60
  text "2" at 5134.5,5689.5 h60
  text "Top Solder" at 5544.41,5689.5 h60
  text "Solder Resist" at 6954,5689.5 h60
  text "0.40mil" at 7813.77,5689.5 h60
  text "3.5" at 8463.6,5689.5 h60
  text "3" at 5134.5,5569.5 h60
  text "Layer 1 - Top Layer" at 5544.41,5569.5 h60
  text "Copper" at 6954,5569.5 h60
  text "1.40mil" at 7813.77,5569.5 h60
  text "4" at 5134.5,5449.5 h60
  text "Dielectric 1" at 5544.41,5449.5 h60
  text "370HR" at 6954,5449.5 h60
  text "10.60mil" at 7813.77,5449.5 h60
  text "4.2" at 8463.6,5449.5 h60
  text "5" at 5134.5,5329.5 h60
  text "Layer 2 - GND" at 5544.41,5329.5 h60
  text "Copper" at 6954,5329.5 h60
  text "1.42mil" at 7813.77,5329.5 h60
  text "6" at 5134.5,5209.5 h60
  text "Dielectric 6" at 5544.41,5209.5 h60
  text "370HR" at 6954,5209.5 h60
  text "8.00mil" at 7813.77,5209.5 h60
  text "4.2" at 8463.6,5209.5 h60
  text "7" at 5134.5,5089.5 h60
  text "Layer 3 - Signal" at 5544.41,5089.5 h60
  text "Copper" at 6954,5089.5 h60
  text "1.42mil" at 7813.77,5089.5 h60
  text "8" at 5134.5,4969.5 h60
  text "Dielectric 3" at 5544.41,4969.5 h60
  text "370HR" at 6954,4969.5 h60
  text "15.60mil" at 7813.77,4969.5 h60
  text "4.2" at 8463.6,4969.5 h60
  text "9" at 5134.5,4849.5 h60
  text "Layer 4 - Signal 2" at 5544.41,4849.5 h60
  text "Copper" at 6954,4849.5 h60
  text "1.42mil" at 7813.77,4849.5 h60
  text "10" at 5134.5,4729.5 h60
  text "Dielectric 4" at 5544.41,4729.5 h60
  text "370HR" at 6954,4729.5 h60
  text "8.00mil" at 7813.77,4729.5 h60
  text "4.2" at 8463.6,4729.5 h60
  text "11" at 5134.5,4609.5 h60
  text "Layer 5 - GND" at 5544.41,4609.5 h60
  text "Copper" at 6954,4609.5 h60
  text "1.42mil" at 7813.77,4609.5 h60
  text "12" at 5134.5,4489.5 h60
  text "Dielectric 5" at 5544.41,4489.5 h60
  text "370HR" at 6954,4489.5 h60
  text "10.60mil" at 7813.77,4489.5 h60
  text "4.2" at 8463.6,4489.5 h60
  text "13" at 5134.5,4369.5 h60
  text "Layer 6 - Bottom Layer" at 5544.41,4369.5 h60
  text "Copper" at 6954,4369.5 h60
  text "1.40mil" at 7813.77,4369.5 h60
  text "14" at 5134.5,4249.5 h60
  text "Bottom Solder" at 5544.41,4249.5 h60
  text "Solder Resist" at 6954,4249.5 h60
  text "0.40mil" at 7813.77,4249.5 h60
  text "3.5" at 8463.6,4249.5 h60
  text "15" at 5134.5,4129.5 h60
  text "Bottom Overlay" at 5544.41,4129.5 h60
  text ".Layer_Name" at -346,-2616.49 h60
M13 Component Bodies Top:
  text ".Layer_Name" at -346,-2616.49 h60
M14 Component Bodies Bottom:
  lines w10: -736,-737 -736,-61 ; -736,-736 -60,-736 -60,-60 -736,-60
  text ".Layer_Name" at -346,-2616.49 h60
M15 Courtyards Top:
  text ".Layer_Name" at -346,-2616.49 h60
M16 Courtyards Bottom:
  text ".Layer_Name" at -346,-2616.49 h60
Drill Drawing:
  circle w10: c640.72,-936.72 r27.63
  lines w10: 613.09,-1530.69 668.34,-1530.69 640.72,-1585.94 613.09,-1530.69 ; 613.09,-1461.62 668.34,-1461.62 668.34,-1406.37 613.09,-1406.37 613.09,-1461.62 ; 613.09,-1323.49 626.9,-1323.49 640.72,-1337.3 654.53,-1323.49 668.34,-1323.49 654.53,-1309.68 668.34,-1295.86 654.53,-1295.86 640.72,-1282.05 626.9,-1295.86 613.09,-1295.86 626.9,-1309.68 613.09,-1323.49 ; 613.09,-1212.98 613.09,-1199.17 626.9,-1185.36 613.09,-1171.54 613.09,-1157.73 626.9,-1157.73 640.72,-1171.54 654.53,-1157.73 668.34,-1157.73 668.34,-1171.54 654.53,-1185.36 668.34,-1199.17 668.34,-1212.98 654.53,-1212.98 640.72,-1199.17 626.9,-1212.98 613.09,-1212.98 ; 613.09,-1061.04 640.72,-1088.66 668.34,-1061.04 640.72,-1033.41 613.09,-1061.04
  lines w12: 563,-1623.24 4263.13,-1623.24 ; 563,-877.32 4263.13,-877.32 ; 900.86,-1747.56 900.86,-753 ; 1232.86,-1747.56 1232.86,-753 ; 1869.43,-1747.56 1869.43,-753 ; 2128.57,-1747.56 2128.57,-753 ; 2503.72,-1747.56 2503.72,-753 ; 3696.7,-1747.56 3696.7,-753 ; 563,-1747.56 4263.13,-1747.56 4263.13,-753 563,-753 563,-1747.56
  text "Symbol" at 637.59,-840.02 h72
  text "Quantity" at 938.16,-840.02 h72
  text "Finished Hole Size" at 1270.16,-840.02 h72
  text "Plated" at 1906.72,-840.02 h72
  text "Hole Type" at 2165.86,-840.02 h72
  text "Drill Layer Pair" at 2541.02,-840.02 h72
  text "Hole Tolerance" at 3733.99,-840.02 h72
  text "2" at 938.16,-964.34 h60
  text "62.99mil (1.600mm)" at 1270.16,-964.34 h60
  text "NPTH" at 1906.72,-964.34 h60
  text "Round" at 2165.86,-964.34 h60
  text "Layer 1 - Top Layer - Layer 6 - Bottom Layer" at 2541.02,-964.34 h60
  text "1" at 938.16,-1088.66 h60
  text "280.00mil (7.112mm)" at 1270.16,-1088.66 h60
  text "NPTH" at 1906.72,-1088.66 h60
  text "Round" at 2165.86,-1088.66 h60
  text "Layer 1 - Top Layer - Layer 6 - Bottom Layer" at 2541.02,-1088.66 h60
  text "137" at 938.16,-1212.98 h60
  text "6.00mil (0.152mm)" at 1270.16,-1212.98 h60
  text "PTH" at 1906.72,-1212.98 h60
  text "Round" at 2165.86,-1212.98 h60
  text "Layer 1 - Top Layer - Layer 6 - Bottom Layer" at 2541.02,-1212.98 h60
  text "9" at 938.16,-1337.3 h60
  text "7.87mil (0.200mm)" at 1270.16,-1337.3 h60
  text "PTH" at 1906.72,-1337.3 h60
  text "Round" at 2165.86,-1337.3 h60
  text "Layer 1 - Top Layer - Layer 6 - Bottom Layer" at 2541.02,-1337.3 h60
  text "1" at 938.16,-1461.62 h60
  text "41.34mil (1.050mm)" at 1270.16,-1461.62 h60
  text "PTH" at 1906.72,-1461.62 h60
  text "Round" at 2165.86,-1461.62 h60
  text "Layer 1 - Top Layer - Layer 6 - Bottom Layer" at 2541.02,-1461.62 h60
  text "4" at 938.16,-1585.94 h60
  text "61.02mil (1.550mm)" at 1270.16,-1585.94 h60
  text "PTH" at 1906.72,-1585.94 h60
  text "Round" at 2165.86,-1585.94 h60
  text "Layer 1 - Top Layer - Layer 6 - Bottom Layer" at 2541.02,-1585.94 h60
  text "154 Total" at 938.16,-1710.26 h60
  text ".Layer_Name" at -346,-2616.49 h60
M17 Embedded Cavity:
  text ".Layer_Name" at -346,-2616.49 h60
M18 Embedded Assembly:
  text ".Layer_Name" at -346,-2616.49 h60
M19 Embedded Keepout:
  text ".Layer_Name" at -346,-2616.49 h60

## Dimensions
-923,-2158 to 77,-2158 on M2 Board Dimensions
-1038.25,121.5 to -653,-1758 on M2 Board Dimensions
-883.25,121.5 to -795.89,-796.14 on M2 Board Dimensions
-0.61,-0.86 to -795.89,-0.86 on M2 Board Dimensions
-0.61,-796.14 to -0.61,-0.86 on M2 Board Dimensions
-925.81,-398.5 to 129.31,-398.5 on M2 Board Dimensions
